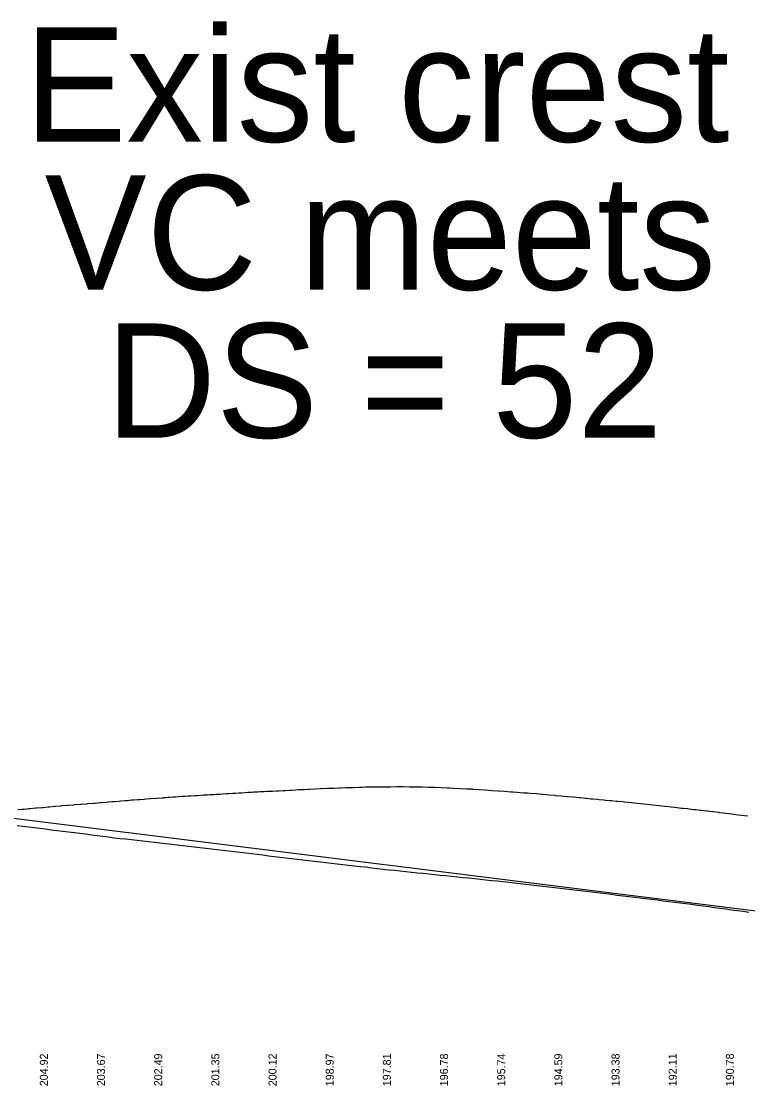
# Model space of a CAD drawing. Extents: x 1838386 to 1955906, y 719739 to 834437.
# Drawn here: x 1881589 to 1882224, y 820601 to 821531 of the extents above; entities that cross this region are included whole.
import ezdxf

# ---------------------------------------------------------------- set-up
doc = ezdxf.new("R2010")
doc.units = 0
for name, color, linetype in [('RD_DDB_Profile_EX', 7, 'Continuous'), ('RD_DDB_Profile_PR', 7, 'Continuous'), ('RD_DDB_StripGrade', 7, 'Continuous'), ('RD_Sketch1', 7, 'Continuous')]:
    doc.layers.add(name, color=color, linetype=linetype)

msp = doc.modelspace()

# ---------------------------------------------------------------- linework, layer by layer
at = {"layer": 'RD_DDB_Profile_EX'}
for points in [[(1881585.15, 820828.15), (1881590.15, 820827.57), (1881595.15, 820827), (1881600.15, 820826.4), (1881605.15, 820825.83), (1881610.15, 820825.11), (1881615.15, 820824.47), (1881620.15, 820823.87), (1881625.15, 820823.28), (1881630.15, 820822.65), (1881635.15, 820821.99), (1881640.15, 820821.36), (1881645.15, 820820.73), (1881650.15, 820820.1), (1881655.15, 820819.49), (1881660.15, 820818.87), (1881665.15, 820818.19), (1881670.15, 820817.49), (1881675.15, 820816.87), (1881680.15, 820816.37), (1881685.15, 820815.81), (1881690.15, 820815.26), (1881695.15, 820814.68), (1881700.15, 820814.09), (1881705.15, 820813.52), (1881710.15, 820812.89), (1881715.15, 820812.32), (1881720.15, 820811.78), (1881725.15, 820811.21), (1881730.15, 820810.59), (1881735.15, 820810.01), (1881740.15, 820809.46), (1881745.15, 820808.9), (1881750.15, 820808.35), (1881755.15, 820807.8), (1881760.15, 820807.25), (1881765.15, 820806.64), (1881770.15, 820806.03), (1881775.15, 820805.42), (1881780.15, 820804.81), (1881785.15, 820804.22), (1881790.15, 820803.64), (1881795.15, 820803.03), (1881800.15, 820802.38), (1881805.15, 820801.75), (1881810.15, 820801.06), (1881815.15, 820800.47), (1881820.15, 820799.94), (1881825.15, 820799.36), (1881830.15, 820798.69), (1881835.15, 820798.1), (1881840.15, 820797.54), (1881845.15, 820796.97), (1881850.15, 820796.41), (1881855.15, 820795.88), (1881860.15, 820795.34), (1881865.15, 820794.75), (1881870.15, 820794.17), (1881875.15, 820793.57), (1881880.15, 820792.99), (1881885.15, 820792.43), (1881890.15, 820791.89)], [(1881890.15, 820791.89), (1881895.15, 820791.26), (1881900.15, 820790.68), (1881905.15, 820790.07), (1881910.15, 820789.47), (1881915.15, 820788.95), (1881920.15, 820788.45), (1881925.15, 820787.92), (1881930.15, 820787.37), (1881935.15, 820786.84), (1881940.15, 820786.36), (1881945.15, 820785.88), (1881950.15, 820785.36), (1881955.15, 820784.84), (1881960.15, 820784.29), (1881965.15, 820783.8), (1881970.15, 820783.32), (1881975.15, 820782.81), (1881980.15, 820782.3), (1881985.15, 820781.75), (1881990.15, 820781.15), (1881995.15, 820780.58), (1882000.15, 820780.08), (1882005.15, 820779.63), (1882010.15, 820779.16), (1882015.15, 820778.61), (1882020.15, 820777.99), (1882025.15, 820777.36), (1882030.15, 820776.79), (1882035.15, 820776.24), (1882040.15, 820775.67), (1882045.15, 820775.08), (1882050.15, 820774.53), (1882055.15, 820774.01), (1882060.15, 820773.44), (1882065.15, 820772.82), (1882070.15, 820772.2), (1882075.15, 820771.61), (1882080.15, 820771.04), (1882085.15, 820770.49), (1882090.15, 820769.9), (1882095.15, 820769.26), (1882100.15, 820768.63), (1882105.15, 820768.01), (1882110.15, 820767.37), (1882115.15, 820766.77), (1882120.15, 820766.14), (1882125.15, 820765.51), (1882130.15, 820764.91), (1882135.15, 820764.29), (1882140.15, 820763.7), (1882145.15, 820763.07), (1882150.15, 820762.36), (1882155.15, 820761.63), (1882160.15, 820760.99), (1882165.15, 820760.43), (1882170.15, 820759.91), (1882175.15, 820759.23), (1882180.15, 820758.57), (1882185.15, 820757.87), (1882190.15, 820757.2), (1882195.15, 820756.51), (1882200.15, 820755.84), (1882205.15, 820755.16), (1882210.15, 820754.45), (1882215.15, 820753.75), (1882220.15, 820753.1), (1882225.15, 820752.41)]]:
    msp.add_lwpolyline(points, dxfattribs=at)
at = {"layer": 'RD_DDB_Profile_PR'}
msp.add_line((1881558.08, 820837.6), (1882275.08, 820748.07), dxfattribs=at)
at = {"layer": 'RD_Sketch1'}
msp.add_lwpolyline([(1881585.92, 820842.05), (1881589.88, 820842.39), (1881591.43, 820842.55), (1881595.37, 820842.96), (1881596.96, 820843.1), (1881601.17, 820843.5), (1881602.51, 820843.59), (1881606.81, 820843.9), (1881608, 820844.02), (1881612.38, 820844.43), (1881613.53, 820844.54), (1881617.99, 820844.96), (1881619.06, 820845.06), (1881623.76, 820845.49), (1881624.57, 820845.57), (1881629.16, 820846.01), (1881630.14, 820846.07), (1881634.78, 820846.35), (1881635.65, 820846.41), (1881640.29, 820846.76), (1881641.16, 820846.83), (1881646.05, 820847.24), (1881646.69, 820847.29), (1881652.21, 820847.73), (1881653.12, 820847.8), (1881657.73, 820848.19), (1881658.97, 820848.3), (1881663.25, 820848.66), (1881664.65, 820848.78), (1881668.77, 820849.13), (1881670.15, 820849.25), (1881674.31, 820849.56), (1881676.01, 820849.69), (1881679.82, 820850), (1881681.63, 820850.15), (1881685.34, 820850.47), (1881687.02, 820850.62), (1881690.89, 820850.88), (1881692.52, 820850.99), (1881696.4, 820851.28), (1881698.24, 820851.42), (1881701.92, 820851.69), (1881702.08, 820851.71), (1881707.45, 820852.12), (1881707.55, 820852.13), (1881712.87, 820852.48), (1881712.98, 820852.49), (1881715.94, 820852.68), (1881717.31, 820852.88), (1881718.5, 820852.96), (1881721.39, 820853.15), (1881724.02, 820853.34), (1881726.57, 820853.52), (1881729.57, 820853.68), (1881731.97, 820853.81), (1881735.08, 820854), (1881737.24, 820854.13), (1881740.6, 820854.34), (1881742.79, 820854.48), (1881746.12, 820854.7), (1881748.34, 820854.84), (1881751.64, 820855.07), (1881753.79, 820855.22), (1881757.19, 820855.39), (1881759.43, 820855.5), (1881762.7, 820855.69), (1881765.25, 820855.83), (1881768.21, 820856.03), (1881770.46, 820856.19), (1881773.74, 820856.4), (1881776.12, 820856.55), (1881779.28, 820856.7), (1881781.48, 820856.81), (1881784.78, 820857.04), (1881787.01, 820857.19), (1881790.31, 820857.4), (1881792.19, 820857.52), (1881795.85, 820857.71), (1881797.79, 820857.8), (1881801.38, 820857.96), (1881803.33, 820858.04), (1881806.9, 820858.21), (1881808.55, 820858.29), (1881812.42, 820858.5), (1881813.97, 820858.58), (1881817.94, 820858.8), (1881819.84, 820858.9), (1881823.46, 820859.09), (1881825.03, 820859.17), (1881828.99, 820859.37), (1881831.41, 820859.49), (1881834.52, 820859.63), (1881836.67, 820859.73), (1881840.04, 820859.89), (1881840.98, 820859.94), (1881845.54, 820860.23), (1881845.73, 820860.25), (1881850.9, 820860.45), (1881851.09, 820860.45), (1881856.47, 820860.68), (1881856.62, 820860.69), (1881861.83, 820860.91), (1881862.14, 820860.92), (1881866.93, 820861.12), (1881867.69, 820861.14), (1881872.57, 820861.25), (1881873.21, 820861.26), (1881877.64, 820861.36), (1881878.7, 820861.41), (1881884.23, 820861.66), (1881886.41, 820861.77), (1881886.56, 820861.77), (1881886.7, 820861.78), (1881886.8, 820861.78), (1881889.79, 820861.83), (1881890.24, 820861.84), (1881895.31, 820861.92), (1881897.47, 820861.96), (1881898.26, 820861.97), (1881900.84, 820862), (1881906.37, 820862.05), (1881908.55, 820862.07), (1881911.43, 820862.1), (1881911.65, 820862.1), (1881911.89, 820862.1), (1881917.42, 820862.15), (1881921.36, 820862.18), (1881921.77, 820862.18), (1881922.97, 820862.16), (1881928.49, 820862.09), (1881934.01, 820862.01), (1881937.8, 820861.95), (1881938.73, 820861.92), (1881939.56, 820861.9), (1881945.08, 820861.72), (1881950.27, 820861.56), (1881950.58, 820861.54), (1881950.62, 820861.54), (1881956.14, 820861.31), (1881961.66, 820861.08), (1881963.02, 820861.02), (1881963.26, 820861.01), (1881967.19, 820860.83), (1881972.72, 820860.58), (1881978.24, 820860.32), (1881983, 820860.1), (1881983.15, 820860.09), (1881983.79, 820860.05), (1881989.31, 820859.68), (1881994.54, 820859.33), (1881994.73, 820859.31), (1881994.84, 820859.3), (1882000.37, 820858.89), (1882005.89, 820858.47), (1882005.94, 820858.47), (1882006.62, 820858.42), (1882011.42, 820858.05), (1882016.94, 820857.62), (1882017.86, 820857.55), (1882018.94, 820857.47), (1882022.45, 820857.24), (1882027.98, 820856.86), (1882030.41, 820856.69), (1882031.58, 820856.6), (1882033.51, 820856.45), (1882039.03, 820856.03), (1882044.56, 820855.6), (1882045.05, 820855.56), (1882050.11, 820855.06), (1882055.39, 820854.53), (1882055.51, 820854.51), (1882055.61, 820854.5), (1882055.61, 820854.5), (1882061.14, 820854.03), (1882066.2, 820853.6), (1882066.66, 820853.56), (1882071.79, 820853.12), (1882072.18, 820853.09), (1882076.86, 820852.7), (1882077.73, 820852.61), (1882082.26, 820852.13), (1882083.26, 820852.02), (1882087.39, 820851.55), (1882088.76, 820851.43), (1882093.04, 820851.04), (1882094.28, 820850.93), (1882098.35, 820850.55), (1882099.81, 820850.4), (1882103.59, 820850.04), (1882105.33, 820849.88), (1882109.07, 820849.55), (1882110.86, 820849.37), (1882114.58, 820849.01), (1882116.39, 820848.83), (1882119.69, 820848.49), (1882121.93, 820848.23), (1882125.1, 820847.86), (1882127.45, 820847.59), (1882130.4, 820847.25), (1882132.94, 820847.02), (1882135.85, 820846.75), (1882138.48, 820846.5), (1882141.06, 820846.25), (1882144.02, 820845.9), (1882146.43, 820845.61), (1882149.54, 820845.26), (1882151.59, 820845.03), (1882155.06, 820844.66), (1882157.18, 820844.43), (1882160.58, 820844.08), (1882162.47, 820843.88), (1882166.12, 820843.45), (1882167.78, 820843.26), (1882171.62, 820842.87), (1882173.08, 820842.72), (1882177.16, 820842.25), (1882178.38, 820842.11), (1882182.69, 820841.57), (1882183.9, 820841.43), (1882188.21, 820840.93), (1882189.04, 820840.84), (1882193.73, 820840.31), (1882194.23, 820840.26), (1882198.68, 820839.71), (1882199.27, 820839.63), (1882202.94, 820839.17), (1882204.77, 820838.97), (1882207.94, 820838.62), (1882210.32, 820838.32), (1882213.69, 820837.88), (1882215.83, 820837.62), (1882218.75, 820837.27), (1882221.33, 820837), (1882224.33, 820836.68)], dxfattribs=at)
msp.add_lwpolyline([(1881585.92, 820842.05), (1881589.88, 820842.39), (1881591.43, 820842.55), (1881595.37, 820842.96), (1881596.96, 820843.1), (1881601.17, 820843.5), (1881602.51, 820843.59), (1881606.81, 820843.9), (1881608, 820844.02), (1881612.38, 820844.43), (1881613.53, 820844.54), (1881617.99, 820844.96), (1881619.06, 820845.06), (1881623.76, 820845.49), (1881624.57, 820845.57), (1881629.16, 820846.01), (1881630.14, 820846.07), (1881634.78, 820846.35), (1881635.65, 820846.41), (1881640.29, 820846.76), (1881641.16, 820846.83), (1881646.05, 820847.24), (1881646.69, 820847.29), (1881652.21, 820847.73), (1881653.12, 820847.8), (1881657.73, 820848.19), (1881658.97, 820848.3), (1881663.25, 820848.66), (1881664.65, 820848.78), (1881668.77, 820849.13), (1881670.15, 820849.25), (1881674.31, 820849.56), (1881676.01, 820849.69), (1881679.82, 820850), (1881681.63, 820850.15), (1881685.34, 820850.47), (1881687.02, 820850.62), (1881690.89, 820850.88), (1881692.52, 820850.99), (1881696.4, 820851.28), (1881698.24, 820851.42), (1881701.92, 820851.69), (1881702.08, 820851.71), (1881707.45, 820852.12), (1881707.55, 820852.13), (1881712.87, 820852.48), (1881712.98, 820852.49), (1881715.94, 820852.68), (1881717.31, 820852.88), (1881718.5, 820852.96), (1881721.39, 820853.15), (1881724.02, 820853.34), (1881726.57, 820853.52), (1881729.57, 820853.68), (1881731.97, 820853.81), (1881735.08, 820854), (1881737.24, 820854.13), (1881740.6, 820854.34), (1881742.79, 820854.48), (1881746.12, 820854.7), (1881748.34, 820854.84), (1881751.64, 820855.07), (1881753.79, 820855.22), (1881757.19, 820855.39), (1881759.43, 820855.5), (1881762.7, 820855.69), (1881765.25, 820855.83), (1881768.21, 820856.03), (1881770.46, 820856.19), (1881773.74, 820856.4), (1881776.12, 820856.55), (1881779.28, 820856.7), (1881781.48, 820856.81), (1881784.78, 820857.04), (1881787.01, 820857.19), (1881790.31, 820857.4), (1881792.19, 820857.52), (1881795.85, 820857.71), (1881797.79, 820857.8), (1881801.38, 820857.96), (1881803.33, 820858.04), (1881806.9, 820858.21), (1881808.55, 820858.29), (1881812.42, 820858.5), (1881813.97, 820858.58), (1881817.94, 820858.8), (1881819.84, 820858.9), (1881823.46, 820859.09), (1881825.03, 820859.17), (1881828.99, 820859.37), (1881831.41, 820859.49), (1881834.52, 820859.63), (1881836.67, 820859.73), (1881840.04, 820859.89), (1881840.98, 820859.94), (1881845.54, 820860.23), (1881845.73, 820860.25), (1881850.9, 820860.45), (1881851.09, 820860.45), (1881856.47, 820860.68), (1881856.62, 820860.69), (1881861.83, 820860.91), (1881862.14, 820860.92), (1881866.93, 820861.12), (1881867.69, 820861.14), (1881872.57, 820861.25), (1881873.21, 820861.26), (1881877.64, 820861.36), (1881878.7, 820861.41), (1881884.23, 820861.66), (1881886.41, 820861.77), (1881886.56, 820861.77), (1881886.7, 820861.78), (1881886.8, 820861.78), (1881889.79, 820861.83), (1881890.24, 820861.84), (1881895.31, 820861.92), (1881897.47, 820861.96), (1881898.26, 820861.97), (1881900.84, 820862), (1881906.37, 820862.05), (1881908.55, 820862.07), (1881911.43, 820862.1), (1881911.65, 820862.1), (1881911.89, 820862.1), (1881917.42, 820862.15), (1881921.36, 820862.18), (1881921.77, 820862.18), (1881922.97, 820862.16), (1881928.49, 820862.09), (1881934.01, 820862.01), (1881937.8, 820861.95), (1881938.73, 820861.92), (1881939.56, 820861.9), (1881945.08, 820861.72), (1881950.27, 820861.56), (1881950.58, 820861.54), (1881950.62, 820861.54), (1881956.14, 820861.31), (1881961.66, 820861.08), (1881963.02, 820861.02), (1881963.26, 820861.01), (1881967.19, 820860.83), (1881972.72, 820860.58), (1881978.24, 820860.32), (1881983, 820860.1), (1881983.15, 820860.09), (1881983.79, 820860.05), (1881989.31, 820859.68), (1881994.54, 820859.33), (1881994.73, 820859.31), (1881994.84, 820859.3), (1882000.37, 820858.89), (1882005.89, 820858.47), (1882005.94, 820858.47), (1882006.62, 820858.42), (1882011.42, 820858.05), (1882016.94, 820857.62), (1882017.86, 820857.55), (1882018.94, 820857.47), (1882022.45, 820857.24), (1882027.98, 820856.86), (1882030.41, 820856.69), (1882031.58, 820856.6), (1882033.51, 820856.45), (1882039.03, 820856.03), (1882044.56, 820855.6), (1882045.05, 820855.56), (1882050.11, 820855.06), (1882055.39, 820854.53), (1882055.51, 820854.51), (1882055.61, 820854.5), (1882055.61, 820854.5), (1882061.14, 820854.03), (1882066.2, 820853.6), (1882066.66, 820853.56), (1882071.79, 820853.12), (1882072.18, 820853.09), (1882076.86, 820852.7), (1882077.73, 820852.61), (1882082.26, 820852.13), (1882083.26, 820852.02), (1882087.39, 820851.55), (1882088.76, 820851.43), (1882093.04, 820851.04), (1882094.28, 820850.93), (1882098.35, 820850.55), (1882099.81, 820850.4), (1882103.59, 820850.04), (1882105.33, 820849.88), (1882109.07, 820849.55), (1882110.86, 820849.37), (1882114.58, 820849.01), (1882116.39, 820848.83), (1882119.69, 820848.49), (1882121.93, 820848.23), (1882125.1, 820847.86), (1882127.45, 820847.59), (1882130.4, 820847.25), (1882132.94, 820847.02), (1882135.85, 820846.75), (1882138.48, 820846.5), (1882141.06, 820846.25), (1882144.02, 820845.9), (1882146.43, 820845.61), (1882149.54, 820845.26), (1882151.59, 820845.03), (1882155.06, 820844.66), (1882157.18, 820844.43), (1882160.58, 820844.08), (1882162.47, 820843.88), (1882166.12, 820843.45), (1882167.78, 820843.26), (1882171.62, 820842.87), (1882173.08, 820842.72), (1882177.16, 820842.25), (1882178.38, 820842.11), (1882182.69, 820841.57), (1882183.9, 820841.43), (1882188.21, 820840.93), (1882189.04, 820840.84), (1882193.73, 820840.31), (1882194.23, 820840.26), (1882198.68, 820839.71), (1882199.27, 820839.63), (1882202.94, 820839.17), (1882204.77, 820838.97), (1882207.94, 820838.62), (1882210.32, 820838.32), (1882213.69, 820837.88), (1882215.83, 820837.62), (1882218.75, 820837.27), (1882221.33, 820837), (1882224.33, 820836.68)], dxfattribs=at)
msp.add_lwpolyline([(1881585.92, 820842.05), (1881589.88, 820842.39), (1881591.43, 820842.55), (1881595.37, 820842.96), (1881596.96, 820843.1), (1881601.17, 820843.5), (1881602.51, 820843.59), (1881606.81, 820843.9), (1881608, 820844.02), (1881612.38, 820844.43), (1881613.53, 820844.54), (1881617.99, 820844.96), (1881619.06, 820845.06), (1881623.76, 820845.49), (1881624.57, 820845.57), (1881629.16, 820846.01), (1881630.14, 820846.07), (1881634.78, 820846.35), (1881635.65, 820846.41), (1881640.29, 820846.76), (1881641.16, 820846.83), (1881646.05, 820847.24), (1881646.69, 820847.29), (1881652.21, 820847.73), (1881653.12, 820847.8), (1881657.73, 820848.19), (1881658.97, 820848.3), (1881663.25, 820848.66), (1881664.65, 820848.78), (1881668.77, 820849.13), (1881670.15, 820849.25), (1881674.31, 820849.56), (1881676.01, 820849.69), (1881679.82, 820850), (1881681.63, 820850.15), (1881685.34, 820850.47), (1881687.02, 820850.62), (1881690.89, 820850.88), (1881692.52, 820850.99), (1881696.4, 820851.28), (1881698.24, 820851.42), (1881701.92, 820851.69), (1881702.08, 820851.71), (1881707.45, 820852.12), (1881707.55, 820852.13), (1881712.87, 820852.48), (1881712.98, 820852.49), (1881715.94, 820852.68), (1881717.31, 820852.88), (1881718.5, 820852.96), (1881721.39, 820853.15), (1881724.02, 820853.34), (1881726.57, 820853.52), (1881729.57, 820853.68), (1881731.97, 820853.81), (1881735.08, 820854), (1881737.24, 820854.13), (1881740.6, 820854.34), (1881742.79, 820854.48), (1881746.12, 820854.7), (1881748.34, 820854.84), (1881751.64, 820855.07), (1881753.79, 820855.22), (1881757.19, 820855.39), (1881759.43, 820855.5), (1881762.7, 820855.69), (1881765.25, 820855.83), (1881768.21, 820856.03), (1881770.46, 820856.19), (1881773.74, 820856.4), (1881776.12, 820856.55), (1881779.28, 820856.7), (1881781.48, 820856.81), (1881784.78, 820857.04), (1881787.01, 820857.19), (1881790.31, 820857.4), (1881792.19, 820857.52), (1881795.85, 820857.71), (1881797.79, 820857.8), (1881801.38, 820857.96), (1881803.33, 820858.04), (1881806.9, 820858.21), (1881808.55, 820858.29), (1881812.42, 820858.5), (1881813.97, 820858.58), (1881817.94, 820858.8), (1881819.84, 820858.9), (1881823.46, 820859.09), (1881825.03, 820859.17), (1881828.99, 820859.37), (1881831.41, 820859.49), (1881834.52, 820859.63), (1881836.67, 820859.73), (1881840.04, 820859.89), (1881840.98, 820859.94), (1881845.54, 820860.23), (1881845.73, 820860.25), (1881850.9, 820860.45), (1881851.09, 820860.45), (1881856.47, 820860.68), (1881856.62, 820860.69), (1881861.83, 820860.91), (1881862.14, 820860.92), (1881866.93, 820861.12), (1881867.69, 820861.14), (1881872.57, 820861.25), (1881873.21, 820861.26), (1881877.64, 820861.36), (1881878.7, 820861.41), (1881884.23, 820861.66), (1881886.41, 820861.77), (1881886.56, 820861.77), (1881886.7, 820861.78), (1881886.8, 820861.78), (1881889.79, 820861.83), (1881890.24, 820861.84), (1881895.31, 820861.92), (1881897.47, 820861.96), (1881898.26, 820861.97), (1881900.84, 820862), (1881906.37, 820862.05), (1881908.55, 820862.07), (1881911.43, 820862.1), (1881911.65, 820862.1), (1881911.89, 820862.1), (1881917.42, 820862.15), (1881921.36, 820862.18), (1881921.77, 820862.18), (1881922.97, 820862.16), (1881928.49, 820862.09), (1881934.01, 820862.01), (1881937.8, 820861.95), (1881938.73, 820861.92), (1881939.56, 820861.9), (1881945.08, 820861.72), (1881950.27, 820861.56), (1881950.58, 820861.54), (1881950.62, 820861.54), (1881956.14, 820861.31), (1881961.66, 820861.08), (1881963.02, 820861.02), (1881963.26, 820861.01), (1881967.19, 820860.83), (1881972.72, 820860.58), (1881978.24, 820860.32), (1881983, 820860.1), (1881983.15, 820860.09), (1881983.79, 820860.05), (1881989.31, 820859.68), (1881994.54, 820859.33), (1881994.73, 820859.31), (1881994.84, 820859.3), (1882000.37, 820858.89), (1882005.89, 820858.47), (1882005.94, 820858.47), (1882006.62, 820858.42), (1882011.42, 820858.05), (1882016.94, 820857.62), (1882017.86, 820857.55), (1882018.94, 820857.47), (1882022.45, 820857.24), (1882027.98, 820856.86), (1882030.41, 820856.69), (1882031.58, 820856.6), (1882033.51, 820856.45), (1882039.03, 820856.03), (1882044.56, 820855.6), (1882045.05, 820855.56), (1882050.11, 820855.06), (1882055.39, 820854.53), (1882055.51, 820854.51), (1882055.61, 820854.5), (1882055.61, 820854.5), (1882061.14, 820854.03), (1882066.2, 820853.6), (1882066.66, 820853.56), (1882071.79, 820853.12), (1882072.18, 820853.09), (1882076.86, 820852.7), (1882077.73, 820852.61), (1882082.26, 820852.13), (1882083.26, 820852.02), (1882087.39, 820851.55), (1882088.76, 820851.43), (1882093.04, 820851.04), (1882094.28, 820850.93), (1882098.35, 820850.55), (1882099.81, 820850.4), (1882103.59, 820850.04), (1882105.33, 820849.88), (1882109.07, 820849.55), (1882110.86, 820849.37), (1882114.58, 820849.01), (1882116.39, 820848.83), (1882119.69, 820848.49), (1882121.93, 820848.23), (1882125.1, 820847.86), (1882127.45, 820847.59), (1882130.4, 820847.25), (1882132.94, 820847.02), (1882135.85, 820846.75), (1882138.48, 820846.5), (1882141.06, 820846.25), (1882144.02, 820845.9), (1882146.43, 820845.61), (1882149.54, 820845.26), (1882151.59, 820845.03), (1882155.06, 820844.66), (1882157.18, 820844.43), (1882160.58, 820844.08), (1882162.47, 820843.88), (1882166.12, 820843.45), (1882167.78, 820843.26), (1882171.62, 820842.87), (1882173.08, 820842.72), (1882177.16, 820842.25), (1882178.38, 820842.11), (1882182.69, 820841.57), (1882183.9, 820841.43), (1882188.21, 820840.93), (1882189.04, 820840.84), (1882193.73, 820840.31), (1882194.23, 820840.26), (1882198.68, 820839.71), (1882199.27, 820839.63), (1882202.94, 820839.17), (1882204.77, 820838.97), (1882207.94, 820838.62), (1882210.32, 820838.32), (1882213.69, 820837.88), (1882215.83, 820837.62), (1882218.75, 820837.27), (1882221.33, 820837), (1882224.33, 820836.68)], dxfattribs=at)

# ---------------------------------------------------------------- texts
at = {"layer": 'RD_DDB_StripGrade'}
for s, p in [('204.92', (1881612.08, 820600.13)), ('203.67', (1881662.08, 820600.13)), ('202.49', (1881712.08, 820600.13)), ('201.35', (1881762.08, 820600.13)), ('200.12', (1881812.08, 820600.13)), ('198.97', (1881862.08, 820600.13)), ('197.81', (1881912.08, 820600.13)), ('196.78', (1881962.08, 820600.13)), ('195.74', (1882012.08, 820600.13)), ('194.59', (1882062.08, 820600.13)), ('193.38', (1882112.08, 820600.13)), ('192.11', (1882162.08, 820600.13)), ('190.78', (1882212.08, 820600.13))]:
    msp.add_text(s, height=7, rotation=90, dxfattribs=at).set_placement(p)
at = {"layer": 'RD_Sketch1'}
for s, p in [('Exist crest', (1881591.61, 821426.1)), ('Exist crest', (1881591.61, 821426.1)), ('Exist crest', (1881591.61, 821426.1)), ('VC meets', (1881609.25, 821296.68)), ('VC meets', (1881609.25, 821296.68)), ('VC meets', (1881609.25, 821296.68)), ('DS = 52', (1881662.65, 821167.26)), ('DS = 52', (1881662.65, 821167.26)), ('DS = 52', (1881662.65, 821167.26))]:
    msp.add_text(s, height=100, dxfattribs=at).set_placement(p)

doc.saveas('drawing.dxf')
